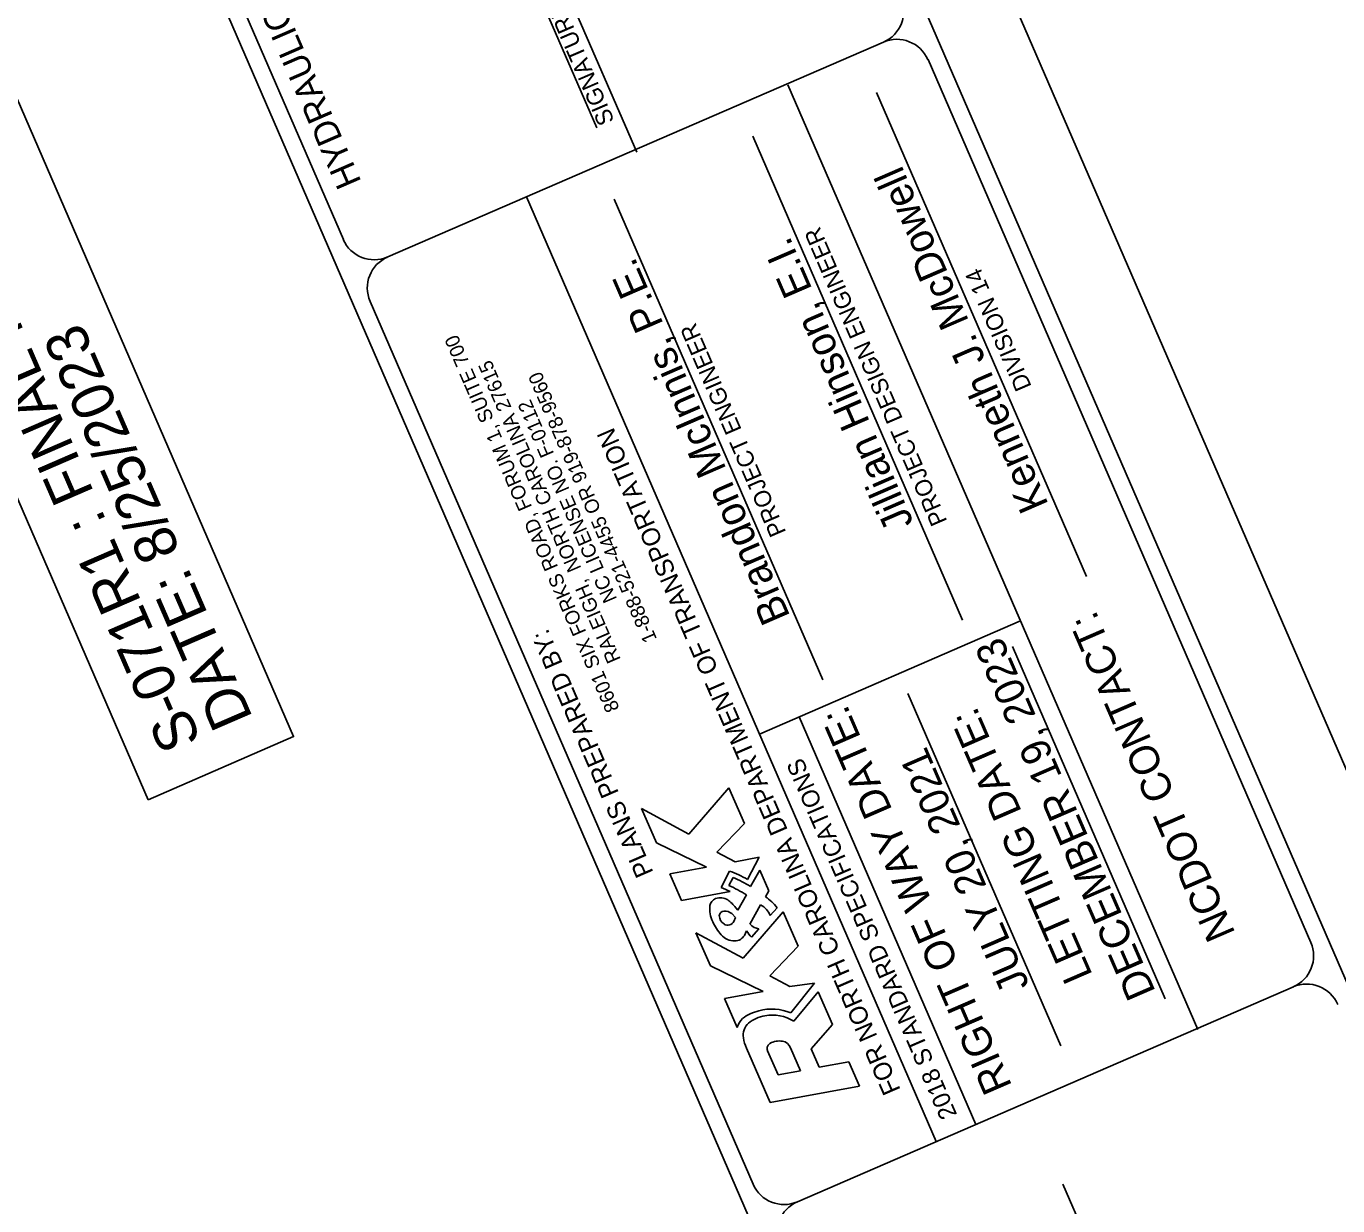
# Model space of a CAD drawing. Extents: x 442728 to 492797, y 479541 to 511293.
# Drawn here: x 478444 to 484269, y 500146 to 505386 of the extents above; entities that cross this region are included whole.
import ezdxf

# ---------------------------------------------------------------- set-up
doc = ezdxf.new("R2010")
doc.units = 0
for name, color, linetype in [('Old_Level_8', 7, 'Continuous'), ('Prop PHM Text', 7, 'Continuous'), ('Sheet Block Title CELL', 7, 'Continuous'), ('Sheet Data Field CELL', 7, 'Continuous'), ('Sheet Plot Border Outside CELL', 7, 'Continuous'), ('Sheet Title CELL', 7, 'Continuous')]:
    doc.layers.add(name, color=color, linetype=linetype)

msp = doc.modelspace()

# ---------------------------------------------------------------- linework, layer by layer
at = {"layer": 'Prop PHM Text'}
msp.add_lwpolyline([(478984.7, 501949.8), (476946.4, 506650.5), (477593, 506930.9), (479631.3, 502230.2)], close=True, dxfattribs=at)
at = {"layer": 'Sheet Block Title CELL'}
for p, q in [((481387.2, 501797.2), (481564.4, 502002)), ((481564.4, 502002), (481633.7, 501843.9)), ((481242.6, 501758.4), (481176, 501910.5)), ((481176, 501910.5), (481387.2, 501797.2)), ((481633.7, 501843.9), (481511, 501717.3)), ((481465.1, 501650.8), (481242.6, 501758.4)), ((481511, 501717.3), (481592.2, 501674.4)), ((481302.9, 501620.7), (481465.1, 501650.8)), ((481592.2, 501674.4), (481699.2, 501694.3)), ((481699.2, 501694.3), (481647.4, 501595.8)), ((481354.7, 501502.5), (481302.9, 501620.7)), ((481567.8, 501632.9), (481530.2, 501559.6)), ((481583, 501604.2), (481564.6, 501568.4)), ((481701.7, 501637.1), (481661.1, 501563.9)), ((481741.8, 501545.6), (481701.7, 501637.1)), ((481569.9, 501542.5), (481354.7, 501502.5)), ((481642.3, 501527.8), (481604, 501459.4)), ((481726.4, 501518.4), (481741.8, 501545.6)), ((481604, 501459.4), (481594.6, 501469.9)), ((481658.2, 501396.9), (481705.2, 501483.2)), ((481748.2, 501434.7), (481778.7, 501470.1)), ((481576.8, 501443.6), (481594, 501426.7)), ((481594, 501426.7), (481586.7, 501408.9)), ((481627.6, 501245.2), (481805.8, 501451.1)), ((481805.8, 501451.1), (481872.5, 501298.8)), ((481482.2, 501211.4), (481418.2, 501357.6)), ((481418.2, 501357.6), (481627.6, 501245.2)), ((481633.3, 501347), (481642.7, 501367.7)), ((481665.3, 501338.5), (481697.9, 501376.3)), ((481872.5, 501298.8), (481745.7, 501168)), ((481716.1, 501098.3), (481482.2, 501211.4)), ((481745.7, 501168), (481835.6, 501120.5)), ((481835.6, 501120.5), (481944.3, 501135.4)), ((481944.3, 501135.4), (481839.5, 501002.6)), ((481545.6, 501066.6), (481716.1, 501098.3)), ((481601.9, 500938.2), (481545.6, 501066.6)), ((481961.4, 501095.6), (481852.4, 500965.4)), ((482025, 500950.6), (481961.4, 501095.6)), ((481929.8, 500843.1), (482025, 500950.6)), ((481642, 500846.5), (481748.3, 500603.8)), ((481838.6, 500847.5), (481883.1, 500745.9)), ((481965.7, 500761.2), (481929.8, 500843.1)), ((481782.9, 500727.3), (481741.8, 500821.3)), ((482097.2, 500785.7), (481965.7, 500761.2)), ((482144.6, 500677.4), (482097.2, 500785.7)), ((481883.1, 500745.9), (481782.9, 500727.3)), ((481748.3, 500603.8), (482144.6, 500677.4))]:
    msp.add_line(p, q, dxfattribs=at)
for centre, radius, start, end in [((481331.9, 501022.4), 654.5, 61.18082, 68.86749), ((481331.9, 501022.4), 633.7, 58.69914, 66.65518), ((481280.6, 500929.3), 677.9, 64.74555, 68.39779), ((481280.6, 500929.3), 699.3, 58.85741, 66.04343), ((481616.4, 501467.9), 137.2, 175.15228, 205.95577), ((481523.4, 501469.1), 44.9, 113.27361, 166.59695), ((481526.4, 501450.7), 63.2, 58.62102, 109.19695), ((481462.3, 501371.1), 165.1, 36.73865, 53.97995), ((481657.7, 501397.8), 97.8, 22.17952, 60.91058), ((481612.5, 501342.4), 209.6, 37.54839, 57.10042), ((481667.9, 501479.9), 189.1, 202.38758, 223.48024), ((481544.2, 501431.8), 22.6, 94.61651, 172.96383), ((481568, 501436.4), 46.2, 182.19901, 237.12674), ((481547.4, 501409.9), 44.7, 48.86933, 96.46675), ((481559.7, 501422.9), 30.4, 236.58655, 332.54063), ((481588, 501397.4), 74.5, 219.70841, 272.09436), ((481830.4, 501489.4), 223.6, 212.96843, 222.41179), ((481703.2, 501435.2), 59.1, 220.44611, 264.79833), ((481592, 501370.4), 47.5, 268.40371, 330.42929), ((481736.1, 500839.3), 176.9, 102.47135, 128.81366), ((481755, 500802.4), 217.3, 67.12443, 105.23444), ((481689.4, 500912.2), 91.4, 134.64628, 163.43154), ((481706.2, 500901.6), 78.1, 134.63892, 187.14777), ((481745, 500843), 147.6, 97.90322, 129.40452), ((481759.6, 500822), 170.8, 57.08369, 101.77673), ((481815.7, 500922.1), 189.4, 189.19727, 203.53256), ((481762.6, 500843.7), 28.5, 124.1055, 208.13544), ((481626, 500770.6), 126.4, 23.65387, 28.13544), ((481788.5, 500790.7), 87.3, 80.79863, 118.70373), ((481794.8, 500830.6), 47, 21.10116, 80.53654)]:
    msp.add_arc(centre, radius, start, end, dxfattribs=at)
at = {"layer": 'Sheet Data Field CELL'}
msp.add_line((485124.2, 495453.1), (483048, 500241.1), dxfattribs=at)
at = {"layer": 'Sheet Plot Border Outside CELL'}
msp.add_lwpolyline([(465175.4, 504729.3), (475224.7, 481554), (490362.8, 488118.1), (480313.5, 511293.4)], close=True, dxfattribs=at)
at = {"layer": 'Sheet Title CELL'}
for p, q in [((486019.5, 490027.9), (477545.7, 509570)), ((481155.6, 504826), (479838.7, 507862.9)), ((479852.3, 504439.1), (478660.1, 507188.4)), ((480977.7, 504935.2), (480116.9, 506920.4)), ((482251.7, 505316), (480049.7, 504361.2)), ((481826.6, 505126.2), (483646.5, 500928.7)), ((483152.7, 502941.5), (482220.2, 505091.8)), ((482602.7, 502746.8), (481670.3, 504897.1)), ((480665.6, 504628.3), (482485.5, 500430.8)), ((481981.3, 502483), (481055.6, 504618.3)), ((481672.4, 500241.7), (479971.6, 504163.9)), ((481700.5, 502241.2), (482859.6, 502743.8)), ((482823.9, 502629.8), (483502.7, 501064.4)), ((482359.8, 502422), (483038.6, 500856.6)), ((481876.1, 502317.3), (482661, 500506.9)), ((482102.1, 501795.7), (482102.1, 501795.7)), ((482699.5, 501639), (482699.5, 501639)), ((481869.6, 500163.7), (484071.6, 501118.5))]:
    msp.add_line(p, q, dxfattribs=at)
for points in [[(488962.7, 490404.9), (480130.8, 510772.7)], [(484149.5, 501315.8), (482449, 505238.1)]]:
    msp.add_lwpolyline(points, dxfattribs=at)
for centre, start, end in [((482191.2, 505453.4), 293.44243, 23.44243), ((482310.5, 505178.1), 23.44243, 113.44243), ((479989.3, 504498.6), 203.44243, 293.44243), ((480108.6, 504223.3), 113.44243, 203.44243), ((484011.3, 501255.9), 293.44243, 23.44243), ((484130.6, 500980.7), 23.44243, 113.44243), ((481809.3, 500301.1), 203.44243, 293.44243), ((481928.7, 500025.9), 113.44243, 203.44243)]:
    msp.add_arc(centre, 150, start, end, dxfattribs=at)

# ---------------------------------------------------------------- texts
at = {"layer": 'Old_Level_8'}
for s, p in [('8601 SIX FORKS ROAD, FORUM 1, SUITE 700', (481079.8, 502354.7)), ('RALEIGH,  NORTH CAROLINA 27615', (481085.3, 502573.1)), ('1-888-521-4455 OR 919-878-9560', (481246.2, 502663.8)), ('NC LICENSE NO. F-0112', (481069, 502841.4))]:
    msp.add_text(s, height=63.146, rotation=113.43784, dxfattribs=at).set_placement(p)
at = {"layer": 'Prop PHM Text'}
for s, p in [('S-071R1 : FINAL ROADWAY PLANS', (479223.3, 502213.8)), ('DATE: 8/25/2023', (479452, 502313))]:
    msp.add_text(s, height=187.5, rotation=113.44058, dxfattribs=at).set_placement(p)
at = {"layer": 'Sheet Data Field CELL'}
for s, p in [('Kenneth J. McDowell', (482985.6, 503260.3)), ('Jillian Hinson, E.I. ', (482386.6, 503178.7)), ('Brandon McInnis, P.E.', (481838.5, 502763.9)), ('DECEMBER 19, 2023', (483461.2, 501096.4)), ('JULY 20, 2021', (482901, 501125.8))]:
    msp.add_text(s, height=131.253, rotation=113.44243, dxfattribs=at).set_placement(p)
at = {"layer": 'Sheet Title CELL'}
for s, height, p in [(' HYDRAULICS ENGINEER', 112.501, (479950.3, 504656.5)), ('SIGNATURE:', 74.99, (481057.6, 504965.4)), ('PROJECT DESIGN ENGINEER', 74.993, (482535.5, 503186.9)), ('DIVISION 14', 74.993, (482910.3, 503785.6)), ('PROJECT ENGINEER', 74.993, (481819.9, 503138.2)), ('FOR NORTH CAROLINA DEPARTMENT OF TRANSPORTATION', 81.001, (482328.2, 500660.3)), ('NCDOT CONTACT:', 131.248, (483815.2, 501356.3)), ('PLANS PREPARED BY:', 81.001, (481230.4, 501626.2)), ('RIGHT OF WAY DATE: ', 131.248, (482823.6, 500677.5)), ('LETTING DATE:', 131.248, (483181.3, 501170.3)), ('2018 STANDARD SPECIFICATIONS', 78.001, (482579.1, 500550.5))]:
    msp.add_text(s, height=height, rotation=113.44243, dxfattribs=at).set_placement(p)

doc.saveas('drawing.dxf')
